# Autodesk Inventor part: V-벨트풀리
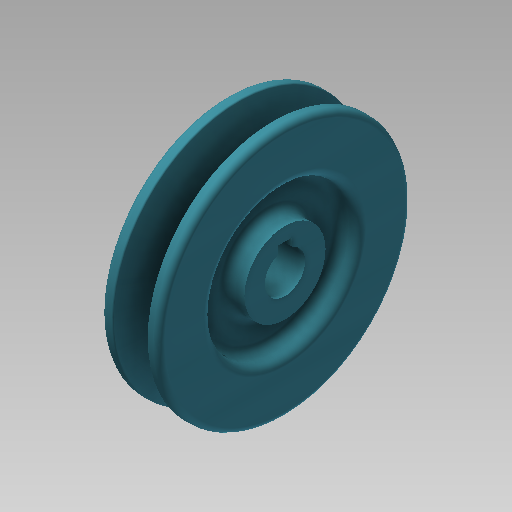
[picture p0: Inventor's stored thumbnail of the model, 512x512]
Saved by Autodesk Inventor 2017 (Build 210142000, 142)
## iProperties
Created: 2019-09
Part Number: V-벨트풀리
Material: 알루미늄 6061
Document SubType Name: Modeling
Designer: mduedu
Density: 1 g/cm^3
Appearance: 커뎃 파란색
Author: mduedu
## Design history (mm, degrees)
sketch "스케치1"
  geometry: L1 (-10, 0)-(10, 0); L2 (10, 0)-(10, 43.5); L3 (10, 43.5)-(-10, 43.5); L4 (-10, 43.5)-(-10, 0); L5 (0, 0)-(0, 43.5); L6 (-5.976, 43.5)-(-2.154, 31); L7 (-2.154, 31)-(2.154, 31); L8 (2.154, 31)-(5.976, 43.5); L9 (-10, 39)-(10, 39); 3 further points
  constraints: 18 end point, 8 point on line, 3 perpendicular, 2 midpoint, 2 parallel, 1 coincident, 1 horizontal, 1 other
  dimensions: "d0" = 87 diameter of L3 L1; "d3" = 12.5 distance between parallel lines of L7 L3; "d4" = 34 deg angle of L8 L6; "d5" = 20 distance between parallel lines of L2 L4; "d6" = 8 distance between parallel lines of L9 L7; "d7" = 9.2 distance of point (4.6, 39) point (-4.6, 39)
revolve "회전1" sketch "스케치1" stored, may be unused: angle "d8" = 90 deg
sketch "스케치2"
  geometry: C1 r 14 at (0, 0); C2 r 25 at (0, 0); 1 further point
  constraints: 2 centre point, 2 coincident
  dimensions: "d9" = 28 diameter of C1; "d10" = 50 diameter of C2
extrude "돌출1" cut sketch "스케치2" distance "d11" = 6; taper "d12" = 0 deg
fillet "모깎기1" dims "d13" = 3
fillet "모깎기2" dims "d14" = 3
fillet "모깎기3" dims "d15" = 0.5, "d16" = 1, "d17" = 2
sketch "스케치3"
  geometry: L1 (-2.5, 6.538)-(2.5, 6.538); L2 (2.5, 6.538)-(2.5, 9.3); L3 (2.5, 9.3)-(-2.5, 9.3); L4 (-2.5, 9.3)-(-2.5, 6.538); A1 r 7 centre (0, 0) between (-2.5, 6.538) and (2.5, 6.538); 1 further point
  constraints: 8 end point, 2 parallel, 2 point on circle, 1 centre point, 1 coincident, 1 horizontal, 1 perpendicular
  dimensions: "d18" = 14 diameter of A1; "d20" = 5 distance of L2.end L3.end; "d21" = 16.3 dimension on A1 L3
extrude "돌출2" cut sketch "스케치3" stored distance "d22" = 6; taper "d23" = 0 deg
node "솔리드1"
mirror "대칭1"
